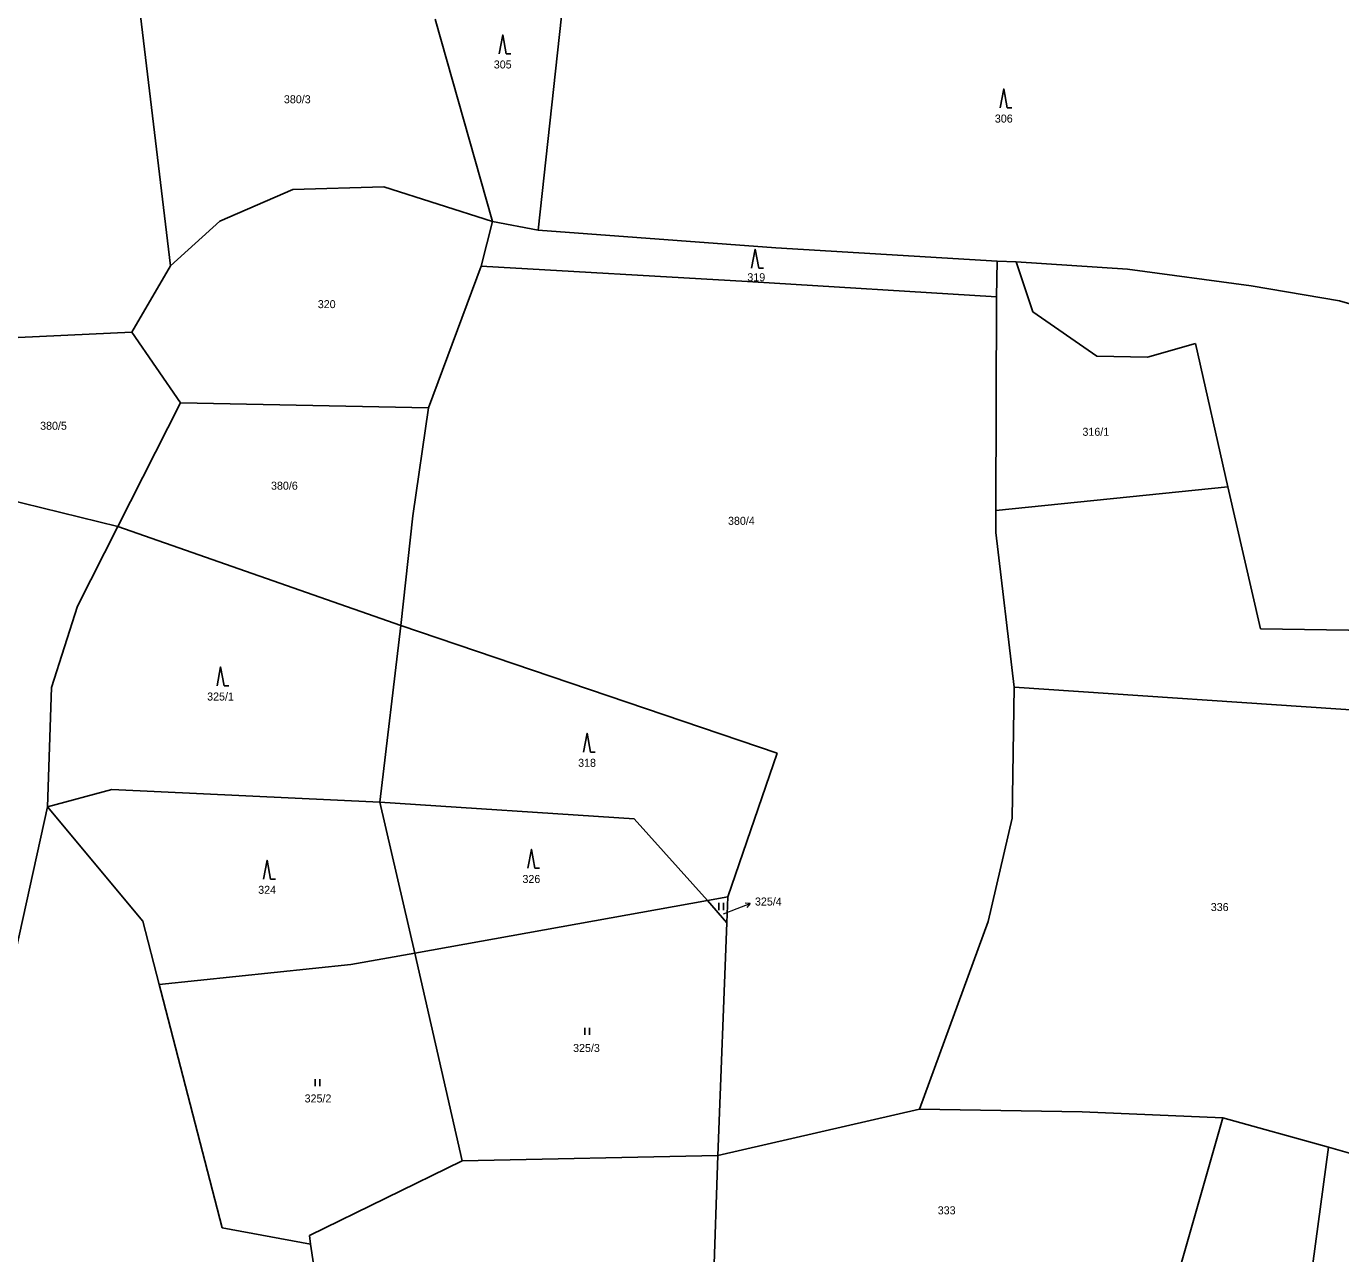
# Model space of a CAD drawing. Extents: x -791548 to -789311, y -1142631 to -1140855.
# Drawn here: x -791130.2 to -790850.9, y -1141959 to -1141698.3 of the extents above; entities that cross this region are included whole.
import ezdxf
from ezdxf.enums import TextEntityAlignment as Align

# ---------------------------------------------------------------- set-up
doc = ezdxf.new("R2010")
doc.units = 0
doc.header["$LTSCALE"] = 0.68
for name, color, linetype, lineweight in [('1', 7, 'Continuous', 25), ('3', 7, 'Continuous', 25), ('7', 7, 'Continuous', 13)]:
    doc.layers.add(name, color=color, linetype=linetype, lineweight=lineweight)
doc.layers.add('2', color=7, linetype='Continuous')

msp = doc.modelspace()

# ---------------------------------------------------------------- linework, layer by layer
at = {"layer": '1'}
for p, q in [((-791099.53, -1141749.19), (-791106.16, -1141694.27)), ((-791043.32, -1141696.76), (-791031.1, -1141739.78)), ((-791089.06, -1141739.67), (-791073.57, -1141732.97)), ((-791073.57, -1141732.97), (-791054.22, -1141732.39)), ((-791054.22, -1141732.39), (-791031.1, -1141739.78)), ((-791099.53, -1141749.19), (-791089.06, -1141739.67)), ((-791031.1, -1141739.78), (-791033.52, -1141749.22)), ((-791031.1, -1141739.78), (-791021.42, -1141741.6)), ((-790923.86, -1141748.15), (-790970.9, -1141745.32)), ((-790924.02, -1141755.77), (-790923.86, -1141748.15)), ((-790923.86, -1141748.15), (-790919.85, -1141748.31)), ((-790919.85, -1141748.31), (-790916.34, -1141758.92)), ((-790919.85, -1141748.31), (-790896.23, -1141749.88)), ((-791107.74, -1141763.23), (-791099.53, -1141749.19)), ((-791033.52, -1141749.22), (-791044.72, -1141779.34)), ((-791033.52, -1141749.22), (-790976.91, -1141752.47)), ((-790896.23, -1141749.88), (-790869.91, -1141753.41)), ((-790976.91, -1141752.47), (-790924.02, -1141755.77)), ((-790869.91, -1141753.41), (-790851.12, -1141756.58)), ((-790924.16, -1141801.11), (-790924.02, -1141755.77)), ((-790851.12, -1141756.58), (-790843.88, -1141758.74)), ((-790916.34, -1141758.92), (-790902.75, -1141768.35)), ((-791143.13, -1141764.92), (-791107.74, -1141763.23)), ((-791097.45, -1141778.3), (-791107.74, -1141763.23)), ((-790891.98, -1141768.57), (-790881.75, -1141765.68)), ((-790881.75, -1141765.68), (-790874.87, -1141796.09)), ((-790902.75, -1141768.35), (-790891.98, -1141768.57)), ((-791110.72, -1141804.53), (-791097.45, -1141778.3)), ((-791044.72, -1141779.34), (-791097.45, -1141778.3)), ((-791044.72, -1141779.34), (-791048.03, -1141802.3)), ((-790874.87, -1141796.09), (-790924.16, -1141801.11)), ((-790874.87, -1141796.09), (-790867.97, -1141826.29)), ((-790924.17, -1141805.8), (-790924.16, -1141801.11)), ((-791048.03, -1141802.3), (-791050.63, -1141825.56)), ((-791119.29, -1141821.46), (-791110.72, -1141804.53)), ((-791050.63, -1141825.56), (-791110.72, -1141804.53)), ((-790920.31, -1141838.67), (-790924.17, -1141805.8)), ((-791124.85, -1141838.74), (-791119.29, -1141821.46)), ((-791050.63, -1141825.56), (-791055.09, -1141863.06)), ((-790970.66, -1141852.67), (-791050.63, -1141825.56)), ((-790867.97, -1141826.29), (-790818.25, -1141826.98)), ((-791125.69, -1141864.1), (-791124.85, -1141838.74)), ((-790920.7, -1141866.47), (-790920.31, -1141838.67)), ((-790920.31, -1141838.67), (-790821.51, -1141845.34)), ((-790981.13, -1141883.22), (-790970.66, -1141852.67)), ((-791112.03, -1141860.4), (-791125.69, -1141864.1)), ((-791055.09, -1141863.06), (-791112.03, -1141860.4)), ((-791133.22, -1141898.19), (-791125.69, -1141864.1)), ((-791125.69, -1141864.1), (-791105.41, -1141888.37)), ((-791047.61, -1141895.14), (-791055.09, -1141863.06)), ((-791001.06, -1141866.6), (-791055.09, -1141863.06)), ((-790985.44, -1141883.99), (-791001.06, -1141866.6)), ((-790925.83, -1141888.47), (-790920.7, -1141866.47)), ((-790985.44, -1141883.99), (-791047.61, -1141895.14)), ((-790981.13, -1141883.22), (-790985.44, -1141883.99)), ((-790985.44, -1141883.99), (-790981.34, -1141888.7)), ((-790981.34, -1141888.7), (-790981.13, -1141883.22)), ((-791101.93, -1141901.83), (-791105.41, -1141888.37)), ((-790983.28, -1141938.11), (-790981.34, -1141888.7)), ((-790940.41, -1141928.27), (-790925.83, -1141888.47)), ((-791047.61, -1141895.14), (-791061.22, -1141897.58)), ((-791047.61, -1141895.14), (-791037.58, -1141939.24)), ((-791061.22, -1141897.58), (-791101.93, -1141901.83)), ((-791101.57, -1141903.2), (-791101.93, -1141901.83)), ((-791101.57, -1141903.2), (-791088.54, -1141953.53)), ((-790983.28, -1141938.11), (-790940.41, -1141928.27)), ((-790905.84, -1141928.85), (-790940.41, -1141928.27)), ((-790875.94, -1141930.15), (-790905.84, -1141928.85)), ((-790888.15, -1141972.78), (-790875.94, -1141930.15)), ((-790853.52, -1141936.36), (-790875.94, -1141930.15)), ((-791037.58, -1141939.24), (-790983.28, -1141938.11)), ((-790983.28, -1141938.11), (-790985.61, -1142009.88)), ((-790863.48, -1142011.16), (-790853.52, -1141936.36)), ((-790853.52, -1141936.36), (-790825.32, -1141944.44)), ((-791070.03, -1141955.15), (-791037.58, -1141939.24)), ((-791088.54, -1141953.53), (-791069.8, -1141956.97)), ((-791069.8, -1141956.97), (-791070.03, -1141955.15)), ((-791069.8, -1141956.97), (-791060.76, -1142017.45))]:
    msp.add_line(p, q, dxfattribs=at)
for points in [[(-790970.9, -1141745.32), (-791021.42, -1141741.6), (-791014.86, -1141681.15)], [(-791110.72, -1141804.53), (-791151.22, -1141794.61), (-791156.16, -1141826.4)]]:
    msp.add_lwpolyline(points, dxfattribs=at)
at = {"layer": '3'}
for p, q in [((-791028.21, -1141704.12), (-791027.214, -1141704.12)), ((-790921.74, -1141715.61), (-790920.744, -1141715.61)), ((-790974.57, -1141749.65), (-790973.574, -1141749.65)), ((-791088.17, -1141838.37), (-791087.174, -1141838.37)), ((-791010.29, -1141852.45), (-791009.294, -1141852.45)), ((-791078.27, -1141879.43), (-791077.274, -1141879.43)), ((-791022.12, -1141877.12), (-791021.124, -1141877.12)), ((-790983.061, -1141886), (-790983.061, -1141884.5)), ((-790982.06, -1141886), (-790982.06, -1141884.5)), ((-791011.531, -1141912.5), (-791011.531, -1141911)), ((-791010.53, -1141912.5), (-791010.53, -1141911)), ((-791068.811, -1141923.41), (-791068.811, -1141921.91)), ((-791067.81, -1141923.41), (-791067.81, -1141921.91))]:
    msp.add_line(p, q, dxfattribs=at)
for points in [[(-791028.21, -1141704.12), (-791028.96, -1141700.12), (-791029.71, -1141704.12)], [(-790921.74, -1141715.61), (-790922.49, -1141711.61), (-790923.24, -1141715.61)], [(-790974.57, -1141749.65), (-790975.32, -1141745.65), (-790976.07, -1141749.65)], [(-791088.17, -1141838.37), (-791088.92, -1141834.37), (-791089.67, -1141838.37)], [(-791010.29, -1141852.45), (-791011.04, -1141848.45), (-791011.79, -1141852.45)], [(-791022.12, -1141877.12), (-791022.87, -1141873.12), (-791023.62, -1141877.12)], [(-791078.27, -1141879.43), (-791079.02, -1141875.43), (-791079.77, -1141879.43)]]:
    msp.add_lwpolyline(points, dxfattribs=at)
at = {"layer": '7'}
msp.add_line((-790976.348, -1141884.635), (-790977.463, -1141884.526), dxfattribs=at)
msp.add_lwpolyline([(-790982.04, -1141886.84), (-790979.15, -1141885.71), (-790976.348, -1141884.635), (-790977.104, -1141885.461)], dxfattribs=at)

# ---------------------------------------------------------------- texts
at = {"layer": '2'}
for s, p in [('305', (-791028.959, -1141707.252)), ('380/3', (-791072.61, -1141714.642)), ('306', (-790922.489, -1141718.742)), ('319', (-790975.079, -1141752.442)), ('320', (-791066.359, -1141758.162)), ('380/5', (-791124.41, -1141783.992)), ('316/1', (-790902.93, -1141785.272)), ('380/6', (-791075.35, -1141796.722)), ('380/4', (-790978.24, -1141804.182)), ('325/1', (-791088.92, -1141841.502)), ('318', (-791011.039, -1141855.582)), ('326', (-791022.869, -1141880.252)), ('324', (-791079.019, -1141882.562)), ('336', (-790876.609, -1141886.222)), ('325/3', (-791011.16, -1141916.152)), ('325/2', (-791068.21, -1141926.872)), ('333', (-790934.629, -1141950.632))]:
    msp.add_text(s, height=1.7, dxfattribs=at).set_placement(p, align=Align.CENTER)
msp.add_text('325/4', height=1.7, dxfattribs=at).set_placement((-790975.36, -1141885.045))

doc.saveas('drawing.dxf')
